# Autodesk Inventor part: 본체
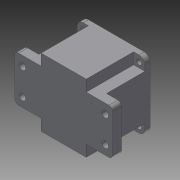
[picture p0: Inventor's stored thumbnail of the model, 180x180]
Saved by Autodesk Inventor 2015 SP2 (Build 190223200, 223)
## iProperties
Created: 2015-06
Part Number: 본체
Material: 일반
Document SubType Name: Modeling
Designer: AMC
Density: 1 g/cm^3
Appearance: 기본값
Author: AMC
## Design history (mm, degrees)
sketch "스케치3"
  geometry: L1 (30, 45)-(-30, 45); L2 (-65, 30)-(-65, -30); L3 (-30, -45)-(30, -45); L4 (65, -30)-(65, 30); L5 (30, 45)-(30, 30); L6 (30, 30)-(65, 30); L7 (65, -30)-(30, -30); L8 (30, -30)-(30, -45); L9 (-30, -45)-(-30, -30); L10 (-30, -30)-(-65, -30); L11 (-30, 45)-(-30, 30); L12 (-30, 30)-(-65, 30); 5 further points
  constraints: 24 end point, 6 point on line, 4 midpoint, 4 parallel, 3 perpendicular, 2 horizontal alignment, 2 vertical alignment, 1 collinear, 1 horizontal, 1 vertical
  dimensions: "d10" = 60 distance of L1.start L1.end; "d11" = 60 distance of L3.start L3.end; "d12" = 60 distance of L4.start L4.end; "d14" = 15 distance of L1.start L5.end; "d16" = 15 distance of L7.end L3.end; "d17" = 130 distance between parallel lines of L2 L4
extrude "돌출3" new body sketch "스케치3" distance "d18" = 12; taper "d19" = 0 deg
sketch "스케치4"
  geometry: L1 (-45, 45)-(45, 45); L2 (45, 45)-(45, -45); L3 (45, -45)-(-45, -45); L4 (-45, -45)-(-45, 45); 3 further points
  constraints: 8 end point, 2 midpoint, 2 parallel, 1 horizontal, 1 horizontal alignment, 1 perpendicular, 1 vertical alignment
  dimensions: "d21" = 90 distance of L3.end L1.start; "d22" = 90 distance of L1.start L1.end
extrude "돌출4" join sketch "스케치4" distance "d23" = 51; taper "d24" = 0 deg
sketch "스케치5"
  geometry: L1 (-45, 45)-(45, 45); L2 (45, 45)-(45, -45); L3 (45, -45)-(-45, -45); L4 (-45, -45)-(-45, 45); 3 further points
  constraints: 8 end point, 2 midpoint, 2 parallel, 1 horizontal, 1 horizontal alignment, 1 perpendicular, 1 vertical alignment
  dimensions: "d25" = 90 distance of L1.start L1.end; "d26" = 90 distance of L3.end L1.start
extrude "돌출5" join sketch "스케치5" distance "d27" = 7; taper "d28" = 0 deg
fillet "모깎기2" dims "d30" = 5
sketch "스케치6"
  geometry: L1 (-30, 45)-(30, 45) reference; L2 (45, 30)-(60, 30) reference; L3 (65, 25)-(65, -25) reference; L4 (60, -30)-(45, -30) reference; L5 (30, -45)-(-30, -45) reference; L6 (-45, -30)-(-60, -30) reference; L7 (-65, -25)-(-65, 25) reference; L8 (-60, 30)-(-45, 30) reference; L9 (-45, -45)-(-45, -30) reference; L10 (-30, -30)-(-45, -30) reference; L11 (-30, -45)-(-30, -30) reference; L12 (30, -30)-(30, -45) reference; L13 (45, -30)-(30, -30) reference; L14 (45, -30)-(45, -45) reference; L15 (45, -45)-(30, -45) reference; L16 (-30, -45)-(-45, -45) reference; L17 (-45, -30)-(-45, 30) reference; L18 (45, 30)-(45, -30) reference; L19 (30, 30)-(45, 30) reference; L20 (30, 45)-(30, 30) reference; L21 (-30, 30)-(-30, 45) reference; L22 (-45, 30)-(-30, 30) reference; L23 (-45, 30)-(-45, 45) reference; L24 (-45, 45)-(-30, 45) reference; L25 (45, 45)-(45, 30) reference; L26 (30, 45)-(45, 45) reference; C1 r 4.5 at (55, 17.5); A1 r 5 centre (60, 25) between (65, 25) and (60, 30) reference; A2 r 5 centre (60, -25) between (60, -30) and (65, -25) reference; A3 r 5 centre (-60, -25) between (-65, -25) and (-60, -30) reference; A4 r 5 centre (-60, 25) between (-60, 30) and (-65, 25) reference; 1 further point
  constraints: 1 centre point
  dimensions: "d32" = 9 diameter of C1; "d33" = 10 distance from line of L3 C1.centre; "d34" = 12.5 distance from line of L2 C1.centre
extrude "돌출6" cut sketch "스케치6" stored distance "d35" = 7; taper "d36" = 0 deg
sketch "스케치7"
  geometry: L1 (-45, -45)-(-45, 45) reference; L2 (-45, 45)-(45, 45) reference; L3 (45, 45)-(45, -45) reference; L4 (45, -45)-(-45, -45) reference; C1 r 3.5 at (37, 37); 2 further points
  constraints: 1 centre point, 1 coincident
  dimensions: "d37" = 7 diameter of C1
extrude "돌출7" cut sketch "스케치7" distance "d38" = 20; taper "d39" = 0 deg
sketch "스케치10"
  geometry: 2 further points
  constraints: 1 coincident
hole "구멍1" sketch "스케치10" at (0, 0) diameter "d48" = 78; stored, may be unused: countersink angle "d52" = 90 deg, drill point angle "d54" = 0 deg; dims "d49" = 6, "d50" = 80, "d51" = 9, "d53" = 61
sketch "스케치11"
  geometry: L1 (-45, -45)-(-45, -30) reference; L2 (-30, -30)-(-45, -30) reference; L3 (-30, -45)-(-30, -30) reference; L4 (30, -45)-(-30, -45) reference; L5 (30, -30)-(30, -45) reference; L6 (45, -30)-(30, -30) reference; L7 (45, -30)-(45, -45) reference; L8 (45, -45)-(30, -45) reference; L9 (-30, -45)-(-45, -45) reference; L10 (-45, -30)-(-45, 30) reference; L11 (-60, 30)-(-45, 30) reference; L12 (-65, -25)-(-65, 25) reference; L13 (-45, -30)-(-60, -30) reference; L14 (60, -30)-(45, -30) reference; L15 (45, 30)-(45, -30) reference; L16 (30, 30)-(45, 30) reference; L17 (30, 45)-(30, 30) reference; L18 (30, 45)-(45, 45) reference; L19 (45, 45)-(45, 30) reference; L20 (45, 30)-(60, 30) reference; L21 (65, 25)-(65, -25) reference; L22 (-45, 30)-(-45, 45) reference; L23 (-45, 45)-(-30, 45) reference; L24 (-30, 45)-(30, 45) reference; L25 (-45, 30)-(-30, 30) reference; L26 (-30, 30)-(-30, 45) reference; L27 (-45, 45)-(-30, 45); L28 (-30, 45)-(-30, 30); L29 (-30, 30)-(-45, 30); L30 (-45, 30)-(-45, 45); C1 r 39 at (0, 0) reference; C2 r 4.5 at (-55, 17.5) reference; C3 r 4.5 at (-55, -17.5) reference; C4 r 4.5 at (55, 17.5) reference; C5 r 4.5 at (55, -17.5) reference; A1 r 5 centre (-60, 25) between (-60, 30) and (-65, 25) reference; A2 r 5 centre (-60, -25) between (-65, -25) and (-60, -30) reference; A3 r 5 centre (60, 25) between (65, 25) and (60, 30) reference; A4 r 5 centre (60, -25) between (60, -30) and (65, -25) reference; 1 further point
  constraints: 8 end point, 2 parallel, 1 horizontal, 1 perpendicular
extrude "돌출9" cut sketch "스케치11" distance "d55" = 51; taper "d56" = 0 deg
sketch "스케치13"
  geometry: L1 (-45, -45)-(-45, -30) reference; L2 (-30, -30)-(-45, -30) reference; L3 (-30, -45)-(-30, -30) reference; L4 (30, -45)-(-30, -45) reference; L5 (30, -30)-(30, -45) reference; L6 (45, -30)-(30, -30) reference; L7 (45, -30)-(45, -45) reference; L8 (45, -45)-(30, -45) reference; L9 (-30, -45)-(-45, -45) reference; L10 (-45, -30)-(-45, 30) reference; L11 (-60, 30)-(-45, 30) reference; L12 (-65, -25)-(-65, 25) reference; L13 (-45, -30)-(-60, -30) reference; L14 (60, -30)-(45, -30) reference; L15 (45, 30)-(45, -30) reference; L16 (30, 30)-(45, 30) reference; L17 (30, 45)-(30, 30) reference; L18 (-30, 45)-(30, 45) reference; L19 (-30, 30)-(-30, 45) reference; L20 (-45, 30)-(-30, 30) reference; L21 (65, 25)-(65, -25) reference; L22 (45, 30)-(60, 30) reference; L23 (45, 45)-(45, 30) reference; L24 (30, 45)-(45, 45) reference; L25 (30, 45)-(45, 45); L26 (45, 45)-(45, 30); L27 (45, 30)-(30, 30); L28 (30, 30)-(30, 45); C1 r 39 at (0, 0) reference; C2 r 4.5 at (-55, 17.5) reference; C3 r 4.5 at (-55, -17.5) reference; C4 r 4.5 at (55, 17.5) reference; C5 r 4.5 at (55, -17.5) reference; A1 r 5 centre (-60, 25) between (-60, 30) and (-65, 25) reference; A2 r 5 centre (-60, -25) between (-65, -25) and (-60, -30) reference; A3 r 5 centre (60, -25) between (60, -30) and (65, -25) reference; A4 r 5 centre (60, 25) between (65, 25) and (60, 30) reference; 1 further point
  constraints: 8 end point, 2 parallel, 1 horizontal, 1 perpendicular
extrude "돌출10" cut sketch "스케치13" distance "d57" = 51; taper "d58" = 0 deg
sketch "스케치14"
  geometry: L1 (-45, -45)-(-45, -30) reference; L2 (-30, -30)-(-45, -30) reference; L3 (-30, -45)-(-30, -30) reference; L4 (30, -45)-(-30, -45) reference; L5 (30, -30)-(30, -45) reference; L6 (45, -30)-(30, -30) reference; L7 (45, -30)-(45, -45) reference; L8 (45, -45)-(30, -45) reference; L9 (-30, -45)-(-45, -45) reference; L10 (-45, -30)-(-45, 30) reference; L11 (-60, 30)-(-45, 30) reference; L12 (-65, -25)-(-65, 25) reference; L13 (-45, -30)-(-60, -30) reference; L14 (60, -30)-(45, -30) reference; L15 (45, 30)-(45, -30) reference; L16 (30, 30)-(45, 30) reference; L17 (30, 45)-(30, 30) reference; L18 (-30, 45)-(30, 45) reference; L19 (-30, 30)-(-30, 45) reference; L20 (-45, 30)-(-30, 30) reference; L21 (65, 25)-(65, -25) reference; L22 (45, 30)-(60, 30) reference; L23 (-45, -30)-(-30, -30); L24 (-30, -30)-(-30, -45); L25 (-30, -45)-(-45, -45); L26 (-45, -45)-(-45, -30); L27 (30, -30)-(45, -30); L28 (45, -30)-(45, -45); L29 (45, -45)-(30, -45); L30 (30, -45)-(30, -30); C1 r 39 at (0, 0) reference; C2 r 4.5 at (-55, 17.5) reference; C3 r 4.5 at (-55, -17.5) reference; C4 r 4.5 at (55, 17.5) reference; C5 r 4.5 at (55, -17.5) reference; A1 r 5 centre (-60, 25) between (-60, 30) and (-65, 25) reference; A2 r 5 centre (-60, -25) between (-65, -25) and (-60, -30) reference; A3 r 5 centre (60, -25) between (60, -30) and (65, -25) reference; A4 r 5 centre (60, 25) between (65, 25) and (60, 30) reference; 1 further point
  constraints: 16 end point, 4 parallel, 2 horizontal, 2 perpendicular
extrude "돌출11" cut sketch "스케치14" distance "d59" = 51; taper "d60" = 0 deg
fillet "모깎기4" dims "d61" = 8
sketch "스케치22"
  geometry: L1 (0, 0)-(-71.893, 0); L2 (0, 0)-(-54.837, 54.837); L3 (-21.763, 27.411)-(-24.429, 30.401); L4 (-27.411, 21.763)-(-30.401, 24.429); A1 r 35 centre (0, 0) between (-24.749, 24.749) and (-21.763, 27.411); A2 r 4 centre (-24.749, 24.749) between (-27.411, 21.763) and (-21.763, 27.411); A3 r 39 centre (0, 0) between (-24.429, 30.401) and (-30.401, 24.429) reference
  constraints: 8 end point, 7 point on circle, 2 centre point, 2 tangent, 1 coincident, 1 horizontal, 1 point on line
  dimensions: "d109" = 45 deg angle of L1 L2; "d110" = 70 diameter of A1; "d111" = 8 diameter of A2
extrude "돌출15" join sketch "스케치22" distance "d112" = 51; taper "d113" = 0 deg
fillet "모깎기7" dims "d114" = 4
fillet "모깎기8" dims "d118" = 2
sketch "스케치23"
  geometry: A1 r 20.5 centre (-11, 0) between (8.117, 7.402) and (8.117, -7.402); A2 r 14 centre (20, 0) between (8.117, -7.402) and (8.117, 7.402); 1 further point
  constraints: 4 point on circle, 2 centre point, 2 horizontal alignment
  dimensions: "d119" = 41 diameter of A1; "d120" = 11 distance of point (0, 0) A1.centre; "d121" = 28 diameter of A2; "d122" = 20 distance of point (0, 0) A2.centre
extrude "돌출16" join sketch "스케치23" distance "d123" = 7; taper "d124" = 0 deg
node "솔리드2"
mirror "대칭1"
mirror "대칭2"
mirror "대칭3"
mirror "대칭4"
pattern_circular "원형 패턴2" dims angle "d116" = 360 deg
node "절단 모서리 투영2"
node "절단 모서리 투영3"
node "절단 모서리 투영7"
node "절단 모서리 투영8"
node "절단 모서리 투영9"
other parameters: "d93" = 7
